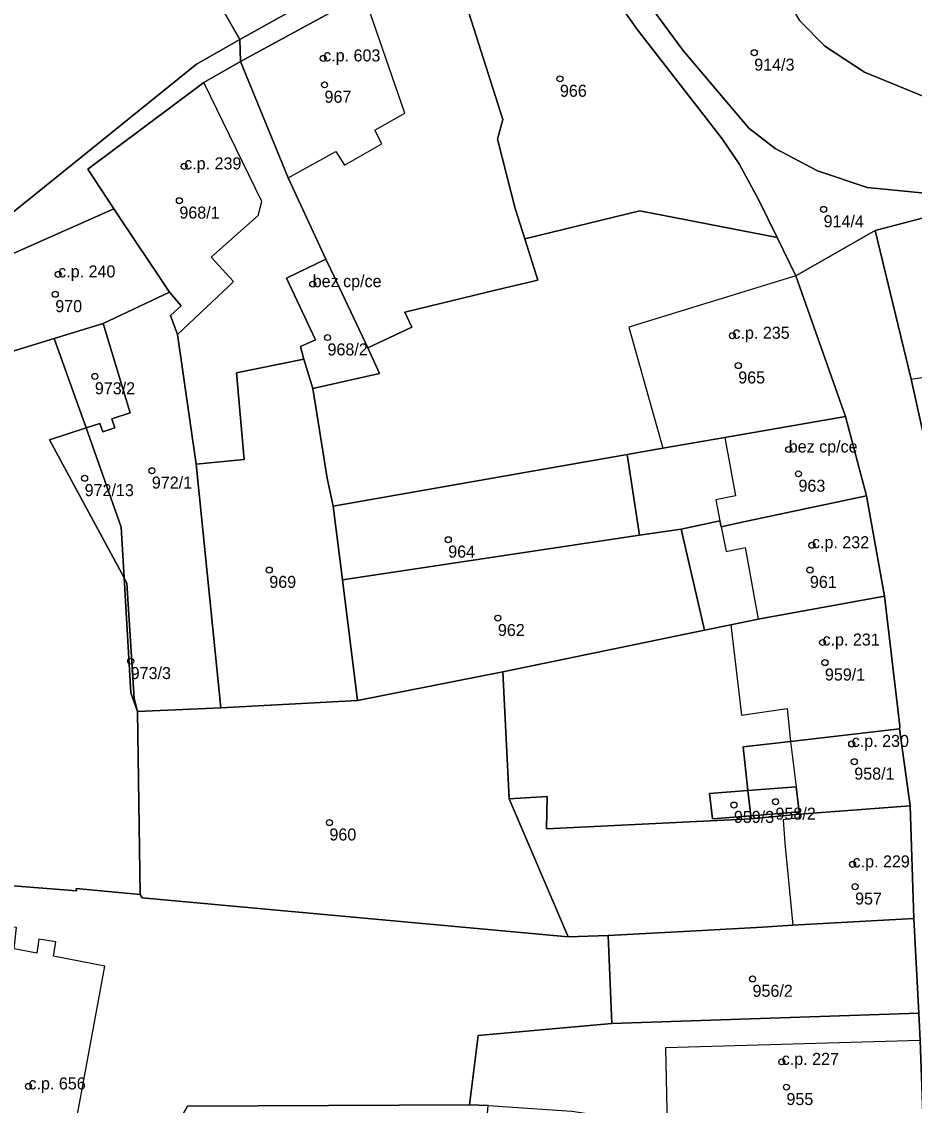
# Model space of a CAD drawing. Extents: x -878211 to -870363, y -1058464 to -1052522.
# Drawn here: x -874899.4 to -874825.1, y -1056399.5 to -1056309.4 of the extents above; entities that cross this region are included whole.
import ezdxf

# ---------------------------------------------------------------- set-up
doc = ezdxf.new("R2010")
doc.units = 0
for name, color, linetype in [('Vrstva 50', 7, 'Continuous'), ('Vrstva 51', 7, 'Continuous'), ('Vrstva 52', 7, 'Continuous')]:
    doc.layers.add(name, color=color, linetype=linetype)

msp = doc.modelspace()

# ---------------------------------------------------------------- linework, layer by layer
at = {"layer": 'Vrstva 50'}
for centre in [(-874874.29, -1056312.45994), (-874838.44, -1056311.98994), (-874854.6, -1056314.15994), (-874874.18, -1056314.65994), (-874885.85, -1056321.43994), (-874886.25, -1056324.28994), (-874832.67, -1056325.00994), (-874896.33, -1056330.41994), (-874875.16, -1056331.22994), (-874896.57, -1056332.06994), (-874873.93, -1056335.66994), (-874840.25, -1056335.51994), (-874839.77, -1056337.99994), (-874893.28, -1056338.89994), (-874835.57, -1056344.97994), (-874888.54, -1056346.73994), (-874894.13, -1056347.36994), (-874834.76, -1056346.99994), (-874863.89, -1056352.47994), (-874833.64, -1056352.93994), (-874878.77, -1056354.99994), (-874833.81, -1056354.99994), (-874859.76, -1056358.99994), (-874832.76, -1056361.02994), (-874890.3, -1056362.57994), (-874832.56, -1056362.69994), (-874830.33, -1056369.45994), (-874830.12, -1056370.93994), (-874840.13, -1056374.53994), (-874836.67, -1056374.26994), (-874873.77, -1056375.99994), (-874830.26, -1056379.47994), (-874830.05, -1056381.32994), (-874838.58, -1056388.99994), (-874836.15, -1056395.89994), (-874898.8, -1056397.93994), (-874835.76, -1056397.99994)]:
    msp.add_circle(centre, 0.25, dxfattribs=at)
at = {"layer": 'Vrstva 51'}
for points in [[(-874886.54, -1056301.59), (-874881.22, -1056310.9), (-874869.66, -1056304.44), (-874863.16, -1056301.35), (-874860.72, -1056300.76), (-874858.1, -1056300.81), (-874842.1, -1056291.88), (-874845.56, -1056281.86), (-874853.69, -1056285.39), (-874853.73, -1056285.82), (-874854.45, -1056288.11), (-874855.71, -1056290.27), (-874857.74, -1056292.06), (-874860.38, -1056293.34), (-874869.56, -1056295.77), (-874877.78, -1056298.18)], [(-874821.24, -1056305.68), (-874820.95, -1056305.48), (-874821.05, -1056305.31), (-874824.38, -1056307.31), (-874825.52, -1056305.39), (-874829.14, -1056307.57), (-874832.24, -1056302.43), (-874825.01, -1056298.2), (-874829.97, -1056300.5), (-874833.03, -1056296.06), (-874834.18, -1056296.79), (-874832.6, -1056300.12), (-874836.12, -1056302.52), (-874835.92, -1056303.06), (-874834.95, -1056305.06), (-874836.72, -1056305.96), (-874834.67, -1056309.32), (-874832.56, -1056311.43), (-874829.27, -1056313.6), (-874823.85, -1056315.82), (-874820.56, -1056316.43), (-874816.79, -1056316.35), (-874816.4, -1056315.83), (-874818.31, -1056311.52)], [(-874881.22, -1056310.9), (-874886.54, -1056301.59), (-874894.54, -1056305.09), (-874895.23, -1056303.94), (-874901.88, -1056307.12), (-874901.47, -1056308.26), (-874902.16, -1056309.87), (-874913.81, -1056324.98), (-874931, -1056340.89), (-874964.95, -1056371.04), (-874960.83, -1056377.33), (-874960.07, -1056376.07), (-874947.65, -1056364.74), (-874921.27, -1056342.74), (-874905.41, -1056329.51), (-874884.82, -1056312.95)], [(-874853.78, -1056304.19), (-874856.17, -1056303.24), (-874858.35, -1056302.75), (-874860.35, -1056302.69), (-874861.94, -1056303.05), (-874863.79, -1056303.61), (-874859.34, -1056317.55), (-874859.8, -1056319.18), (-874858.31, -1056324.95), (-874857.51, -1056327.46), (-874847.95, -1056325.13), (-874836.53, -1056327.36), (-874838.05, -1056324.25), (-874839.69, -1056321.22), (-874841.11, -1056319.16), (-874842.64, -1056317.17), (-874848.15, -1056310.07), (-874849.9, -1056307.62), (-874851.58, -1056305.71)], [(-874874.06, -1056329.15), (-874873.66, -1056330.02), (-874870.59, -1056336.52), (-874866.91, -1056334.8), (-874867.49, -1056333.55), (-874859.74, -1056331.67), (-874856.43, -1056330.89), (-874857.51, -1056327.46), (-874858.31, -1056324.95), (-874859.8, -1056319.18), (-874859.34, -1056317.55), (-874863.79, -1056303.61), (-874870.91, -1056307.13), (-874881.17, -1056312.72), (-874877.21, -1056322.39)], [(-874874.06, -1056329.15), (-874877.21, -1056322.39), (-874881.17, -1056312.72), (-874884.21, -1056314.45), (-874893.86, -1056321.68), (-874891.71, -1056324.96), (-874887.08, -1056331.9), (-874886.11, -1056333.02), (-874886.99, -1056333.83), (-874886.42, -1056335.42), (-874884.86, -1056346.19), (-874880.86, -1056345.81), (-874881.5, -1056338.61), (-874875.89, -1056337.46), (-874876.19, -1056336.42), (-874874.93, -1056335.85), (-874877.34, -1056330.74)], [(-874891.71, -1056324.96), (-874904.55, -1056330.66), (-874902.38, -1056337.5), (-874896.66, -1056335.74), (-874892.58, -1056334.49), (-874887.08, -1056331.9)], [(-874869.62, -1056338.67), (-874875.15, -1056339.91), (-874873.96, -1056347.36), (-874873.45, -1056349.69), (-874849.01, -1056345.4), (-874846.05, -1056344.88), (-874840.88, -1056343.98), (-874830.86, -1056342.24), (-874834.97, -1056330.54), (-874836.53, -1056327.36), (-874847.95, -1056325.13), (-874857.51, -1056327.46), (-874856.43, -1056330.89), (-874859.74, -1056331.67), (-874867.49, -1056333.55), (-874866.91, -1056334.8), (-874870.59, -1056336.52)], [(-874818.46, -1056341.67), (-874819.29, -1056338.18), (-874819.32, -1056337.55), (-874822.04, -1056325.11), (-874828.39, -1056326.76), (-874825.4, -1056339.14), (-874824.48, -1056343.25)], [(-874875.15, -1056339.91), (-874869.62, -1056338.67), (-874870.59, -1056336.52), (-874873.66, -1056330.02), (-874874.06, -1056329.15), (-874877.34, -1056330.74), (-874874.93, -1056335.85), (-874876.19, -1056336.42), (-874875.89, -1056337.46)], [(-874902.38, -1056337.5), (-874904.55, -1056330.66), (-874920.25, -1056343.56), (-874916.29, -1056347.79), (-874914.41, -1056363.17), (-874912.67, -1056362.96), (-874912.47, -1056364.43), (-874908.45, -1056363.89), (-874912.87, -1056376.5), (-874920.12, -1056379.07), (-874920.55, -1056383.05), (-874918.12, -1056382.02), (-874905.74, -1056380.82), (-874894.82, -1056381.67), (-874894.83, -1056381.48), (-874889.5, -1056381.99), (-874889.73, -1056366.76), (-874890.3, -1056365.2), (-874890.85, -1056355.65), (-874897.04, -1056344.18), (-874894.01, -1056343.19), (-874896.66, -1056335.74)], [(-874886.99, -1056333.83), (-874886.11, -1056333.02), (-874887.08, -1056331.9), (-874892.58, -1056334.49), (-874890.35, -1056341.92), (-874891.87, -1056342.43), (-874891.61, -1056343.19), (-874892.62, -1056343.52), (-874892.86, -1056342.81), (-874894.01, -1056343.19), (-874891.1, -1056351.44), (-874890.85, -1056355.65), (-874890.62, -1056356.09), (-874890, -1056365.68), (-874889.73, -1056366.76), (-874882.81, -1056366.46), (-874884.86, -1056346.19), (-874886.42, -1056335.42)], [(-874896.66, -1056335.74), (-874894.01, -1056343.19), (-874892.86, -1056342.81), (-874892.62, -1056343.52), (-874891.61, -1056343.19), (-874891.87, -1056342.43), (-874890.35, -1056341.92), (-874892.58, -1056334.49)], [(-874884.86, -1056346.19), (-874882.81, -1056366.46), (-874871.44, -1056365.85), (-874872.69, -1056355.83), (-874873.45, -1056349.69), (-874873.96, -1056347.36), (-874875.15, -1056339.91), (-874875.89, -1056337.46), (-874881.5, -1056338.61), (-874880.86, -1056345.81)], [(-874829.1, -1056348.82), (-874830.86, -1056342.24), (-874840.88, -1056343.98), (-874846.05, -1056344.88), (-874849.01, -1056345.4), (-874847.98, -1056352.11), (-874844.51, -1056351.59), (-874841.29, -1056350.91), (-874841.19, -1056351.4), (-874839.59, -1056351.06)], [(-874894.01, -1056343.19), (-874897.04, -1056344.18), (-874890.85, -1056355.65), (-874891.1, -1056351.44)], [(-874847.98, -1056352.11), (-874849.01, -1056345.4), (-874873.45, -1056349.69), (-874872.69, -1056355.83)], [(-874827.6, -1056357.18), (-874829.1, -1056348.82), (-874839.59, -1056351.06), (-874841.19, -1056351.4), (-874841.29, -1056350.91), (-874844.51, -1056351.59), (-874842.57, -1056360.01), (-874840.39, -1056359.56), (-874838.11, -1056359.09)], [(-874871.44, -1056365.85), (-874859.36, -1056363.48), (-874848.07, -1056361.15), (-874842.57, -1056360.01), (-874844.51, -1056351.59), (-874847.98, -1056352.11), (-874872.69, -1056355.83)], [(-874890.85, -1056355.65), (-874890.3, -1056365.2), (-874889.73, -1056366.76), (-874890, -1056365.68), (-874890.62, -1056356.09)], [(-874838.73, -1056375.44), (-874841.92, -1056375.7), (-874842.16, -1056373.57), (-874838.96, -1056373.33), (-874839.37, -1056369.69), (-874835.42, -1056369.27), (-874826.37, -1056368.2), (-874826.34, -1056367.98), (-874827.6, -1056357.18), (-874838.11, -1056359.09), (-874840.39, -1056359.56), (-874842.57, -1056360.01), (-874848.07, -1056361.15), (-874859.36, -1056363.48), (-874858.81, -1056374.02), (-874855.66, -1056373.84), (-874855.71, -1056376.53), (-874838.7, -1056375.68)], [(-874889.73, -1056366.76), (-874889.5, -1056381.99), (-874889.34, -1056382.25), (-874853.91, -1056385.5), (-874858.81, -1056374.02), (-874859.36, -1056363.48), (-874871.44, -1056365.85), (-874882.81, -1056366.46)], [(-874839.37, -1056369.69), (-874838.96, -1056373.33), (-874834.95, -1056373.03), (-874834.69, -1056375.11), (-874838.73, -1056375.44), (-874838.7, -1056375.68), (-874834.67, -1056375.3), (-874825.47, -1056374.6), (-874826.37, -1056368.2), (-874835.42, -1056369.27)], [(-874838.73, -1056375.44), (-874838.96, -1056373.33), (-874842.16, -1056373.57), (-874841.92, -1056375.7)], [(-874838.96, -1056373.33), (-874838.73, -1056375.44), (-874834.69, -1056375.11), (-874834.95, -1056373.03)], [(-874834.67, -1056375.3), (-874838.7, -1056375.68), (-874855.71, -1056376.53), (-874855.66, -1056373.84), (-874858.81, -1056374.02), (-874853.91, -1056385.5), (-874850.58, -1056385.39), (-874843.27, -1056385), (-874837.74, -1056384.7), (-874835.24, -1056384.52), (-874825.18, -1056383.98), (-874825.47, -1056374.6)], [(-874923.91, -1056412.98), (-874894.75, -1056420.85), (-874893.04, -1056416.51), (-874890.82, -1056408.96), (-874885.57, -1056399.58), (-874862.13, -1056399.47), (-874861.41, -1056393.71), (-874850.27, -1056392.72), (-874850.58, -1056385.39), (-874853.91, -1056385.5), (-874889.34, -1056382.25), (-874889.5, -1056381.99), (-874894.83, -1056381.48), (-874894.82, -1056381.67), (-874905.74, -1056380.82), (-874918.12, -1056382.02), (-874920.55, -1056383.05), (-874924.5, -1056401.21)], [(-874837.74, -1056384.7), (-874843.27, -1056385), (-874850.58, -1056385.39), (-874850.27, -1056392.72), (-874824.76, -1056391.85), (-874825.18, -1056383.98), (-874835.24, -1056384.52)], [(-874862.13, -1056399.47), (-874860.57, -1056399.52), (-874853.61, -1056399.99), (-874845.68, -1056401.18), (-874841.61, -1056401.26), (-874824.39, -1056400.97), (-874824.63, -1056394.12), (-874824.76, -1056391.85), (-874850.27, -1056392.72), (-874861.41, -1056393.71)], [(-874862.13, -1056399.47), (-874885.57, -1056399.58), (-874890.82, -1056408.96), (-874863.85, -1056410.72), (-874861.51, -1056410.81), (-874860.57, -1056399.52)]]:
    msp.add_lwpolyline(points, close=True, dxfattribs=at)
for points in [[(-874869.66, -1056304.44), (-874881.22, -1056310.9), (-874881.17, -1056312.72), (-874870.91, -1056307.13)], [(-874849.9, -1056307.62), (-874848.15, -1056310.07), (-874842.64, -1056317.17), (-874841.11, -1056319.16), (-874839.69, -1056321.22), (-874838.05, -1056324.25), (-874836.53, -1056327.36), (-874834.97, -1056330.54), (-874828.39, -1056326.76), (-874822.04, -1056325.11), (-874815.38, -1056323.63), (-874815.74, -1056322.36), (-874820.44, -1056323.31), (-874824.26, -1056323.66), (-874829.04, -1056323.18), (-874833.17, -1056321.81), (-874836.69, -1056319.95), (-874838.9, -1056318.27), (-874844.39, -1056311.78), (-874848.34, -1056306.37)], [(-874848.34, -1056306.37), (-874844.39, -1056311.78), (-874838.9, -1056318.27), (-874836.69, -1056319.95), (-874833.17, -1056321.81), (-874829.04, -1056323.18), (-874824.26, -1056323.66), (-874820.44, -1056323.31), (-874815.74, -1056322.36), (-874816.79, -1056316.35), (-874820.56, -1056316.43), (-874823.85, -1056315.82), (-874829.27, -1056313.6), (-874832.56, -1056311.43), (-874834.67, -1056309.32)], [(-874966.7, -1056402.29), (-874963.08, -1056389.92), (-874959.76, -1056378.53), (-874955.45, -1056374.28), (-874955.21, -1056374.1), (-874948.4, -1056368.02), (-874940.77, -1056361.21), (-874934.66, -1056355.77), (-874928.49, -1056350.54), (-874920.25, -1056343.56), (-874904.55, -1056330.66), (-874891.71, -1056324.96), (-874893.86, -1056321.68), (-874884.21, -1056314.45), (-874881.17, -1056312.72), (-874881.22, -1056310.9), (-874884.82, -1056312.95), (-874905.41, -1056329.51), (-874921.27, -1056342.74), (-874947.65, -1056364.74), (-874960.07, -1056376.07), (-874960.83, -1056377.33), (-874968.09, -1056398.43), (-874970.41, -1056405.77)], [(-874817.16, -1056400.09), (-874817.14, -1056390.64), (-874817.23, -1056386.28), (-874817.23, -1056381), (-874817.3, -1056377.31), (-874817.98, -1056368.21), (-874818.43, -1056366.7), (-874819.16, -1056364.21), (-874822.26, -1056351.51), (-874822.74, -1056349.57), (-874824.48, -1056343.25), (-874825.4, -1056339.14), (-874828.39, -1056326.76), (-874834.97, -1056330.54), (-874830.86, -1056342.24), (-874829.1, -1056348.82), (-874827.6, -1056357.18), (-874826.34, -1056367.98), (-874826.37, -1056368.2), (-874825.47, -1056374.6), (-874825.18, -1056383.98), (-874824.76, -1056391.85), (-874824.63, -1056394.12), (-874824.39, -1056400.97)]]:
    msp.add_lwpolyline(points, dxfattribs=at)
at = {"layer": 'Vrstva 52'}
for points in [[(-874881.17, -1056312.72), (-874877.21, -1056322.39), (-874873.23, -1056320.2), (-874872.53, -1056321.33), (-874869.4, -1056319.55), (-874870, -1056318.43), (-874867.5, -1056317.02), (-874870.91, -1056307.13)], [(-874887.08, -1056331.9), (-874886.11, -1056333.02), (-874886.99, -1056333.83), (-874886.42, -1056335.42), (-874882.15, -1056331.4), (-874881.75, -1056331.02), (-874883.61, -1056328.99), (-874879.7, -1056325.52), (-874879.39, -1056324.36), (-874884.21, -1056314.45), (-874893.86, -1056321.68), (-874891.71, -1056324.96)], [(-874904.55, -1056330.66), (-874902.38, -1056337.5), (-874896.66, -1056335.74), (-874892.58, -1056334.49), (-874887.08, -1056331.9), (-874891.71, -1056324.96)], [(-874819.32, -1056337.55), (-874822.04, -1056325.11), (-874828.39, -1056326.76), (-874825.4, -1056339.14), (-874819.29, -1056338.18)], [(-874875.89, -1056337.46), (-874875.15, -1056339.91), (-874869.62, -1056338.67), (-874870.59, -1056336.52), (-874873.66, -1056330.02), (-874874.06, -1056329.15), (-874877.34, -1056330.74), (-874874.93, -1056335.85), (-874876.19, -1056336.42)], [(-874848.88, -1056334.8), (-874846.05, -1056344.88), (-874840.88, -1056343.98), (-874830.86, -1056342.24), (-874834.97, -1056330.54)], [(-874839.99, -1056348.83), (-874841.64, -1056349.17), (-874841.29, -1056350.91), (-874841.19, -1056351.4), (-874839.59, -1056351.06), (-874829.1, -1056348.82), (-874830.86, -1056342.24), (-874840.88, -1056343.98)], [(-874841.19, -1056351.4), (-874840.77, -1056353.46), (-874839.2, -1056353.14), (-874838.11, -1056359.09), (-874827.6, -1056357.18), (-874829.1, -1056348.82), (-874839.59, -1056351.06)], [(-874840.39, -1056359.56), (-874839.51, -1056367.07), (-874835.71, -1056366.52), (-874835.45, -1056368.97), (-874835.42, -1056369.27), (-874826.37, -1056368.2), (-874826.34, -1056367.98), (-874827.6, -1056357.18), (-874838.11, -1056359.09)], [(-874835.42, -1056369.27), (-874834.95, -1056373.03), (-874834.69, -1056375.11), (-874834.67, -1056375.3), (-874825.47, -1056374.6), (-874826.37, -1056368.2)], [(-874836.04, -1056375.76), (-874835.89, -1056377.71), (-874835.24, -1056384.52), (-874825.18, -1056383.98), (-874825.47, -1056374.6), (-874834.67, -1056375.3), (-874834.7, -1056375.62)], [(-874919.29, -1056391.92), (-874919.61, -1056394.29), (-874915.96, -1056394.74), (-874915.61, -1056392.19), (-874905.02, -1056392.98), (-874901.98, -1056393.2), (-874904.11, -1056404.76), (-874906.24, -1056416.24), (-874898.07, -1056417.7), (-874895.86, -1056406.18), (-874894.55, -1056399.35), (-874892.45, -1056387.93), (-874896.72, -1056387.12), (-874896.52, -1056385.93), (-874897.95, -1056385.7), (-874898.12, -1056386.86), (-874899.99, -1056386.5), (-874899.81, -1056384.72), (-874918.34, -1056382.71)], [(-874845.83, -1056394.73), (-874845.68, -1056401.18), (-874841.61, -1056401.26), (-874824.39, -1056400.97), (-874824.63, -1056394.12)]]:
    msp.add_lwpolyline(points, close=True, dxfattribs=at)

# ---------------------------------------------------------------- texts
at = {"layer": 'Vrstva 50'}
for s, p in [('c.p. 603', (-874874.29, -1056312.71)), ('914/3', (-874838.44, -1056313.479)), ('966', (-874854.6, -1056315.649)), ('967', (-874874.18, -1056316.149)), ('c.p. 239', (-874885.85, -1056321.69)), ('968/1', (-874886.25, -1056325.779)), ('914/4', (-874832.67, -1056326.499)), ('c.p. 240', (-874896.33, -1056330.669)), ('bez cp/ce', (-874875.16, -1056331.48)), ('970', (-874896.57, -1056333.559)), ('c.p. 235', (-874840.25, -1056335.77)), ('968/2', (-874873.93, -1056337.159)), ('965', (-874839.77, -1056339.489)), ('973/2', (-874893.28, -1056340.389)), ('bez cp/ce', (-874835.57, -1056345.23)), ('972/1', (-874888.54, -1056348.229)), ('963', (-874834.76, -1056348.489)), ('972/13', (-874894.13, -1056348.859)), ('964', (-874863.89, -1056353.969)), ('c.p. 232', (-874833.64, -1056353.19)), ('969', (-874878.77, -1056356.489)), ('961', (-874833.81, -1056356.489)), ('962', (-874859.76, -1056360.489)), ('c.p. 231', (-874832.76, -1056361.28)), ('973/3', (-874890.3, -1056364.069)), ('959/1', (-874832.56, -1056364.189)), ('c.p. 230', (-874830.33, -1056369.71)), ('958/1', (-874830.12, -1056372.429)), ('959/3', (-874840.13, -1056376.029)), ('958/2', (-874836.67, -1056375.759)), ('960', (-874873.77, -1056377.489)), ('c.p. 229', (-874830.26, -1056379.73)), ('957', (-874830.05, -1056382.819)), ('956/2', (-874838.58, -1056390.489)), ('c.p. 227', (-874836.15, -1056396.149)), ('c.p. 656', (-874898.8, -1056398.19)), ('955', (-874835.76, -1056399.489))]:
    msp.add_text(s, height=0.999996, dxfattribs=at).set_placement(p)

doc.saveas('drawing.dxf')
